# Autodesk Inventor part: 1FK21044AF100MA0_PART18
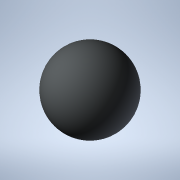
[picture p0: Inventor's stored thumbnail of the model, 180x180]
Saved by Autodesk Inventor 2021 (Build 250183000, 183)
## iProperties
Created: 2025-04
Part Number: 1FK21044AF100MA0_PART18
Material: Generic
Catalog Web Link: www.3dfindit.com
Description: -Servo synchronous motor
Document SubType Name: Modeling
Designer: psAdmin
Mass: 0.137258 g
Surface Area: 1.2868 cm^2
Volume: 0.137258 cm^3
Density: 1 g/cm^3
Appearance: PSOLRGB-212-217-219
Category: PARTsolutions
Title: 1FK21044AF100MA0_PART18
Author: Cadenas PARTsolutions
Comments: Servo synchronous motor
Sending System: PARTsolutions
Preprocessor: ST-DEVELOPER v19.3
PSOL_IDENT_0: {$CADENAS_DATA/23d-libs/siemens_ag/_cat_/ec/e4/1fk21044af100ma0.prj},216 {VTYP=3D},{NB=1FK21044AF100
PSOL_IDENT_1: MA0_PART18},{LINA=1FK21044AF100MA0_PART18},{NN=1FK21044AF100MA0_PART18},{NOPRJ=TRUE},{DATE=19.08.202
PSOL_IDENT_2: 5 14:01:05},{GEOMDATE=30.07.2025 02:01:01},{VERSION=},{LINEID=10},{WBVAR=},{WBNUMERIC=}  {NB=1FK2104
PSOL_IDENT_3: 4AF100MA0_PART18},{LINA=1FK21044AF100MA0_PART18},{KT=DUMMY},{PREVIEW=../../../_pool_/cb/72/p_d211_xx
PSOL_IDENT_4: _00434j.png},{DESCSHORT=SIMOTICS S-1FK2 HD, SINAMICS S210 3AC 400V-480V, 1.27 Nm, 3000 rpm},{DESCLON
PSOL_IDENT_5: G=SIMOTICS S-1FK2 HD servo motor M0=1.27 Nm; PN = 0.4 kW at nN=3000 rpm (380-480 V); PN = 0.2 kW at
PSOL_IDENT_6: nN=1500 rpm (200-240 V); with holding brake; degree of protection IP64; cylindrical shaft D19x40mm;
PSOL_IDENT_7: absolute encoder 22-bit + 12-bit multiturn (encoder AM22DQC); with OCC interface; plug size M17, rot
PSOL_IDENT_8: atable; SIMOTICS S-1FK2 servomotorfor a wide range of uses in industrial environments. SIMOTICS S‑1F
PSOL_IDENT_9: K2 servomotors are compact synchronous motors with a high dynamic performance that set themselves ap
PSOL_IDENT_10: art as a result of their high power density, degree of protection and overload capability. The motor
PSOL_IDENT_11: s are available in two variants: as High Dynamic variant (highest dynamic performance as a result of
PSOL_IDENT_12: the low intrinsic moment of inertia for applications demanding a high dynamic performance with low
PSOL_IDENT_13: moved masses) - and as Compact variant (precise and stable closed-loop control for medium up to larg
PSOL_IDENT_14: e moved masses as a result of a medium intrinsic moment of inertia). SIMOTICSS‑1FK2 servomotors full
PSOL_IDENT_15: y exploit their strengths in a system with the SINAMICSS210 frequency converter and simple connectio
PSOL_IDENT_16: n using the one cable connection (OCC). Advantages include the short control and positioning times,
PSOL_IDENT_17: fast and precise correction of disturbing quantities as well as stable control with a high dynamic p
PSOL_IDENT_18: erformance. The servo motors can be configured to address a wide range of requirements. For example
PSOL_IDENT_19: with and without holding brake, IP64 or IP65 degree of protection, singleturn or multiturn absolute
PSOL_IDENT_20: encoders - to name just a few. Further, the servomotors are available in different shaft heights ext
PSOL_IDENT_21: ending from 20 to 100. A shaft sealing ring is available to achieve an IP65 degree of protection and
PSOL_IDENT_22: for subsequent mounting at the motor or as spare part. SIMOTICS - the optimum motor for each and ev
PSOL_IDENT_23: ery motion control application.},{INTNO=195125043275},{SUPPLIERALTNO=1FK2104-4AF10-0MA0},{MANUID=1FK
PSOL_IDENT_24: 21044AF100MA0},{MANUNAME=Siemens},{MANUTYPEDESC=Synchronous motor 1FK2-HD 1.27 NM},{AAU732=SIMOTICS}
PSOL_IDENT_25: ,{AAO057=S-1FK2},{AAU734=SIMOTICS S-1FK2 HD servo motor M0=1.27 Nm; PN = 0.4 kW at nN=3000 rpm (380-
PSOL_IDENT_26: 480 V); PN = 0.2 kW at nN=1500 rpm (200-240 V); with holding brake; degree of protection IP64; cylin
PSOL_IDENT_27: drical shaft D19x40mm; absolute encoder 22-bit + 12-bit multiturn (encoder AM22DQC); with OCC interf
PSOL_IDENT_28: ace; plug size M17, rotatable;},{AAW338=Synchronous motor 1FK2-HD 1.27 NM},{AAO742=SIMOTICS},{AAO663=
PSOL_IDENT_29: 4042948694015},{NOCUPEROU=1},{PRICEQUANTITY=1},{QUANTITYMIN=1},{QUANTITYINT=1},{CTN=85015100},{COO=D
PSOL_IDENT_30: E},{AAO676=1FK2104-4AF10-0MA0},{AAO677=Siemens AG},{ORDERUNIT=C62},{CONTENTUNIT=C62}
NB: 1FK21044AF100MA0_PART18
NT: Servo synchronous motor
NBSYN: $MANUID._PART18
LINA: 1FK21044AF100MA0_PART18
CATALOG: SIEMENS
PREVIEW: ../../../_pool_/cb/72/p_d211_xx_00434j.png
DESCSHORT: SIMOTICS S-1FK2 HD, SINAMICS S210 3AC 400V-480V, 1.27 Nm, 3000 rpm
DESCLONG: SIMOTICS S-1FK2 HD servo motor M0=1.27 Nm; PN = 0.4 kW at nN=3000 rpm (380-480 V); PN = 0.2 kW at nN=1500 rpm (200-240 V); with holding brake; degree of protect
INTNO: 195125043275
SUPPLIERALTNO: 1FK2104-4AF10-0MA0
MANUID: 1FK21044AF100MA0
MANUNAME: Siemens
MANUTYPEDESC: Synchronous motor 1FK2-HD 1.27 NM
AAU732: SIMOTICS
AAO057: S-1FK2
AAU734: SIMOTICS S-1FK2 HD servo motor M0=1.27 Nm; PN = 0.4 kW at nN=3000 rpm (380-480 V); PN = 0.2 kW at nN=1500 rpm (200-240 V); with holding brake; degree of protect
AAW338: Synchronous motor 1FK2-HD 1.27 NM
AAO742: SIMOTICS
AAO663: 4042948694015.0
NOCUPEROU: 1
PRICEQUANTITY: 1
QUANTITYMIN: 1
QUANTITYINT: 1
CTN: 85015100
COO: DE
ARTICLENO: 1FK21044AF100MA0_PART18
BOMINFO: 1FK21044AF100MA0_PART18
CREATOR: CADENAS GmbH
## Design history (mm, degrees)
feature "2025_04_17_15_33_01_0673"
body "Solid1"
